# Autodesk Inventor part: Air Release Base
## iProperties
Created: 2010-02
Part Number: Air Release Base
Document SubType Name: Modeling
Designer: jgehrig
Density: 1 g/cm^3
Author: jgehrig
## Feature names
1. Extrusion1
2. Extrusion2
